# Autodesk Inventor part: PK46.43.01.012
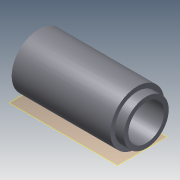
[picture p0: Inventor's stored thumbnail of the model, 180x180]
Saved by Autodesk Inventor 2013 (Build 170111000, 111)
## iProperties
Created: 2005-04
Part Number: PK46.43.01.012
Document SubType Name: Modeling
Designer: elarisa
Manufacturer: Standard
Standards Organization: Custom
Material: Steel, Mild
Density: 7.86 g/cm^3
Author: elarisa
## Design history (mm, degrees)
sketch "Эскиз1"
  geometry: L1 (-16.532, 5.23)-(-16.532, 20.23); L2 (-16.532, 20.23)-(38.468, 20.23); L3 (43.468, 17.73)-(43.468, 5.23); L4 (-16.532, 5.23)-(43.468, 5.23); L5 (43.468, 15.23)-(-6.532, 15.23); L6 (-6.532, 15.23)-(-12.305, 5.23); L7 (43.468, 17.73)-(38.468, 17.73); L8 (38.468, 17.73)-(38.468, 20.23)
  constraints: 16 end point, 3 parallel, 3 perpendicular, 2 point on line, 1 vertical
  dimensions: "d7" = 30 diameter of L2 L4; "d8" = 20 diameter of L5 L4; "d9" = 120 deg angle of L5 L6; "d11" = 50 distance of L5.start L5.end; "d22" = 5 distance of L3.start L7.end; "d23" = 25 diameter of L7 L4; "d24" = 60 distance between parallel lines of L1 L3
revolve "Вращение1" sketch "Эскиз1" stored, may be unused: angle "d12" = 90 deg
node "РабПлоскость1"
sketch "Эскиз2"
  geometry: L1 (-27.5, -15)-(27.5, -15) reference; L2 (-27.5, 15)-(27.5, 15) reference; L3 (27.5, -15)-(27.5, 15) reference; L4 (32.5, -12.5)-(32.5, 12.5) reference; L5 (-27.5, -15)-(-27.5, 15) reference; 1 further point
  dimensions: "d13" = 15 distance from line of L1 point (-7.5, 0); "d27" = 20 distance from line of point (-7.5, 0) L5
hole "Отверстие1" sketch "Эскиз2" diameter "d15" = 20; stored, may be unused: countersink angle "d19" = 90 deg, drill point angle "d21" = 118 deg; dims "d16" = 6, "d17" = 26, "d18" = 3, "d20" = 15
body "Solid1"
